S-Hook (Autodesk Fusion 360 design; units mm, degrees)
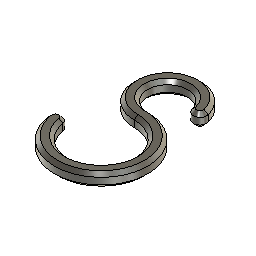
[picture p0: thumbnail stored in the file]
parameter "HookADiameter" = 30
parameter "HookBDiameter" = 50
parameter "Thickness" = 10
parameter "HookAOuter" = 50 (= "HookADiameter + Thickness * 2")
parameter "HookBOuter" = 70 (= "HookBDiameter + Thickness * 2")
parameter "HookAOpeningAngle" = 90
parameter "HookBOpeningAngle" = 90 (= "HookAOpeningAngle")
sketch "Sketch1" plane through (0, 0, 0) normal (0, 0, 1) x axis (1, 0, 0)
  line L1 (0, 20) -> (0, 0)
  line L2 (0, -30) -> (0, 0)
  line L3 (25, 20) -> (0, 20)
  line L4 (-35, -30) -> (0, -30)
  circle C1 centre (0, 20) radius 25
  circle C2 centre (0, -30) radius 35
  circle C3 centre (0, 20) radius 15
  circle C4 centre (0, -30) radius 25
  point P1 (0, 0)
  point P2 (0, 0)
  point P3 (0, 20)
  point P4 (0, 20)
  point P5 (0, 0)
  point P6 (0, -30)
  point P7 (0, -30)
  point P10 (0, 20)
  point P11 (25, 20)
  point P9 (0, -30)
  point P12 (0, -30)
  point P13 (-35, -30)
  coincident P1 P2
  vertical L1
  coincident P3 P4
  coincident P1 P5
  parallel L1 L2
  coincident P6 P7
  concentric C1 C3
  concentric C2 C4
  coincident P4 P10
  coincident C1 P11
  coincident P9 P12
  coincident C2 P13
  dimension "d6" distance P2 P3 = 20 (= "( HookAOuter - Thickness ) / 2")
  dimension "d7" diameter C1 = 50 (= "HookAOuter")
  dimension "d8" distance P5 P6 = 30 (= "( HookBOuter - Thickness ) / 2")
  dimension "d9" diameter C2 = 70 (= "HookBOuter")
  dimension "d10" diameter C3 = 30 (= "HookADiameter")
  dimension "d11" diameter C4 = 50 (= "HookBDiameter")
  dimension "d12" angle L1 L3 = 90
  dimension "d16" angle L2 L4 = 90 (= "HookBOpeningAngle")
extrude "Extrude1" new body sketch "Sketch1" along normal blind 10 (= "Thickness") bodies "S-Hook"
fillet "Fillet1" radius 5 (= "Thickness / 2")
chamfer "Chamfer1" distance 2.5 (= "Thickness / 4")
named bodies: "S-Hook"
